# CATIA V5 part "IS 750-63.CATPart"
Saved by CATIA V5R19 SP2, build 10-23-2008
Part number: IS 750-63
Bounding box of the stored display mesh (mm): x -24.865 to 24.865, y -24.997 to 24.997, z 0 to 222
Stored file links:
  C:\Users\Bora\Desktop\3D Katı model\IS serisi\IS 750\IS 750-63.CATPart
  C:\Program Files\Dassault Systemes\B19\intel_a\reffiles\standard\MetricThickPitch.txt
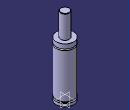
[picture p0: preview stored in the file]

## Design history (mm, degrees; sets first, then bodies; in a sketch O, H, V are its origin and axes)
Body1 (main body)
  Sketch1 on yz-plane, origin (0, 0, 0), H (0, 1, 0), V (0, 0, 1)
    point P3 (12.5, 221)
    point P5 (12.5, 221)
    point P10 (25, 139.5)
    point P11 (25, 143.5)
    point P13 (25, 143.5)
    point P14 (25, 139.5)
    line L1 (25, 0) -> (25, 8)
    line L2 (12.5, 221) -> (12.5, 156)
    arc A1 centre (11.5, 221) radius 1 from (12.5, 221) to (11.5, 222) ccw
    line L3 (21.5, 13) -> (21.5, 8)
    line L4 (25, 13) -> (25, 139.5)
    line L5 (25, 143.5) -> (25, 156)
    arc A2 centre (25, 141.5) radius 2 from (25, 143.5) to (25, 139.5) ccw
    line L6 (11.5, 222) -> (0, 222)
    point P15 (0, 222)
    line L7 (12.5, 156) -> (25, 156)
    line L8 (0, 0) -> (25, 0)
    line L9 (21.5, 13) -> (25, 13)
    line L10 (21.5, 8) -> (25, 8)
    coincidence: P15 V, P3 P5, P10 P14, P11 P13
    tangency: L6 A1
    horizontal: L7 H, L8 H, L9 H, L10 H
  Shaft1: profile Sketch1, axis Sketch1.V, angle 360
  Sketch2 on face of Shaft1 from Sketch1.L8, origin (0, 0, 0), H (1, 0, 0), V (0, -1, 0)
    point P1 (10, 0)
    distance P1 V = 10
  Hole1: placed by Sketch2, at (10, 0, 0) direction (0, 0, 1), diameter 6.647, depth 13, threaded "M8", thread diameter 8, thread depth 13, pitch 1.25
  Sketch3 on face of Shaft1 from Sketch1.L8, origin (0, 0, 0), H (1, 0, 0), V (0, -1, 0)
    point P1 (-10, 0)
    distance P1 V = 10
  Hole2: placed by Sketch3, at (-10, 0, 0) direction (0, 0, 1), diameter 6.647, depth 13, threaded "M8", thread diameter 8, thread depth 13, pitch 1.25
